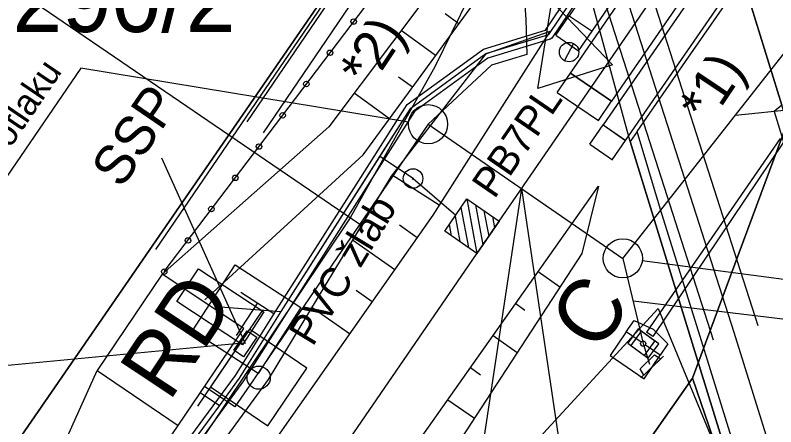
# Model space of a CAD drawing. Extents: x -558199 to -558019, y -1073463 to -1073248.
# Drawn here: x -558155.77 to -558136.35, y -1073413.56 to -1073403.06 of the extents above; entities that cross this region are included whole.
import ezdxf

# ---------------------------------------------------------------- set-up
doc = ezdxf.new("R2010")
doc.units = 0
for name, color, linetype in [('Default', 7, 'Continuous'), ('DWG-zabzař', 7, 'Continuous'), ('El2015-Svršek - součást', 7, 'Continuous'), ('El2015-Zabzař nadzemní', 7, 'Continuous'), ('Elektro nadzemní', 7, 'Continuous'), ('Kolej', 7, 'Continuous'), ('Komunikace', 7, 'Continuous'), ('Nová kabelizace', 7, 'Continuous'), ('nové prvky ZZ', 7, 'Continuous'), ('Plot - zábradlí', 7, 'Continuous'), ('PS01_PS02_nové prvky ZZ', 7, 'Continuous'), ('Přejezd - štěrkové lože', 7, 'Continuous'), ('Sdělovací objekt', 7, 'Continuous'), ('Sonda - šrafa - vrstevnice', 7, 'Continuous'), ('Stavba', 7, 'Continuous'), ('Svazek obcí údolí Desné', 7, 'Continuous'), ('Svazek obcí-chráničky', 7, 'Continuous'), ('Svazek obcí-elektro', 7, 'Continuous'), ('Svazek obcí-zabezpečovací', 7, 'Continuous'), ('Svazek obcí-zabezpečovací_nadzemní', 7, 'Continuous'), ('Svršek součást', 7, 'Continuous'), ('Terén', 7, 'Continuous'), ('Vrstva 15', 7, 'Continuous'), ('Vrstva 18', 7, 'Continuous'), ('zab zař nové popis a prvky', 7, 'Continuous'), ('ŠPVS - kanalizace', 7, 'Continuous')]:
    doc.layers.add(name, color=color, linetype=linetype)

msp = doc.modelspace()

# ---------------------------------------------------------------- linework, layer by layer
at = {"layer": 'Default'}
for p, q in [((-558141.959, -1073403.569), (-558141.62, -1073403.074)), ((-558141.62, -1073403.074), (-558141.038, -1073403.468)), ((-558141.377, -1073403.963), (-558141.038, -1073403.468)), ((-558141.959, -1073403.569), (-558141.38, -1073403.966)), ((-558154.086, -1073404.411), (-558157.347, -1073409.172)), ((-558141.926, -1073405.034), (-558141.587, -1073404.539)), ((-558141.587, -1073404.539), (-558140.536, -1073405.256)), ((-558141.926, -1073405.034), (-558140.875, -1073405.751)), ((-558140.875, -1073405.751), (-558140.536, -1073405.256)), ((-558141.094, -1073406.353), (-558140.755, -1073405.858)), ((-558140.755, -1073405.858), (-558140.178, -1073406.254)), ((-558141.094, -1073406.353), (-558140.517, -1073406.749)), ((-558140.519, -1073406.752), (-558140.18, -1073406.257))]:
    msp.add_line(p, q, dxfattribs=at)
for points in [[(-558130.328, -1073420.145), (-558131.489, -1073419.211), (-558132.265, -1073417.928), (-558133.167, -1073415.078), (-558134.705, -1073410.166), (-558136.19, -1073405.354), (-558137.19, -1073402.13), (-558138.301, -1073398.037), (-558138.619, -1073396.923), (-558140.033, -1073392.586), (-558141.446, -1073388.086), (-558141.737, -1073387.169), (-558144.083, -1073379.873)], [(-558134.819, -1073423.23), (-558136.982, -1073416.266), (-558138.481, -1073411.422), (-558140.066, -1073406.285), (-558141.174, -1073402.236), (-558142.21, -1073398.929), (-558143.82, -1073393.811), (-558145.559, -1073388.359), (-558147.912, -1073380.994)]]:
    msp.add_lwpolyline(points, dxfattribs=at)
at = {"layer": 'DWG-zabzař'}
for p, q in [((-558142.8, -1073399.77), (-558145.05, -1073404.38)), ((-558145.05, -1073404.38), (-558147.21, -1073408.23)), ((-558147.21, -1073408.23), (-558154.78, -1073419.51))]:
    msp.add_line(p, q, dxfattribs=at)
at = {"layer": 'El2015-Svršek - součást'}
for p, q in [((-558144.233, -1073407.749), (-558143.975, -1073409.139)), ((-558144.383, -1073407.967), (-558144.194, -1073408.989)), ((-558144.014, -1073407.899), (-558143.825, -1073408.921)), ((-558144.533, -1073408.186), (-558144.412, -1073408.839)), ((-558143.796, -1073408.049), (-558143.675, -1073408.702)), ((-558143.577, -1073408.199), (-558143.525, -1073408.483)), ((-558144.683, -1073408.404), (-558144.631, -1073408.688))]:
    msp.add_line(p, q, dxfattribs=at)
msp.add_lwpolyline([(-558143.409, -1073408.315), (-558143.975, -1073409.139), (-558144.799, -1073408.573), (-558144.233, -1073407.749)], close=True, dxfattribs=at)
at = {"layer": 'El2015-Zabzař nadzemní'}
msp.add_line((-558145.621, -1073407.249), (-558145.593, -1073407.207), dxfattribs=at)
msp.add_circle((-558145.607, -1073407.228), 0.25, dxfattribs=at)
at = {"layer": 'Elektro nadzemní'}
msp.add_lwpolyline([(-558151.637, -1073410.369), (-558151.088, -1073409.534), (-558149.417, -1073410.633), (-558149.966, -1073411.468), (-558151.637, -1073410.369)], dxfattribs=at)
at = {"layer": 'Kolej'}
msp.add_lwpolyline([(-558166.192, -1073441.436), (-558164.779, -1073439.38), (-558155.66, -1073426.127), (-558147.216, -1073413.854), (-558143.692, -1073408.727), (-558141.06, -1073404.904), (-558137.302, -1073399.438), (-558134.569, -1073395.461), (-558131.717, -1073391.307), (-558124.893, -1073381.375), (-558115.4, -1073367.564), (-558109.636, -1073359.184)], dxfattribs=at)
at = {"layer": 'Komunikace'}
for points in [[(-558134.582, -1073423.154), (-558136.753, -1073416.165), (-558138.246, -1073411.366), (-558139.293, -1073408.016), (-558139.888, -1073406.031), (-558138.651, -1073404.246), (-558137.19, -1073402.13), (-558136.19, -1073405.354), (-558136.385, -1073405.515), (-558134.943, -1073410.228), (-558133.406, -1073415.122), (-558132.477, -1073418.012), (-558131.667, -1073419.37), (-558130.464, -1073420.348)], [(-558139.888, -1073406.031), (-558140.066, -1073406.285), (-558138.481, -1073411.422), (-558136.982, -1073416.266), (-558134.819, -1073423.23)]]:
    msp.add_lwpolyline(points, dxfattribs=at)
at = {"layer": 'Nová kabelizace'}
msp.add_line((-558140.251, -1073409.265), (-558139.73, -1073411.44), dxfattribs=at)
for points in [[(-558143.327, -1073399.376), (-558144.071, -1073400.565), (-558142.86, -1073401.332), (-558142.728, -1073403.163), (-558142.702, -1073404.06), (-558143.604, -1073404.335), (-558145.224, -1073405.842), (-558149.771, -1073412.504), (-558150.161, -1073413.052), (-558150.928, -1073412.531)], [(-558145.224, -1073405.842), (-558140.251, -1073409.265), (-558135.564, -1073403.303), (-558135.378, -1073404.935)]]:
    msp.add_lwpolyline(points, dxfattribs=at)
at = {"layer": 'nové prvky ZZ'}
for p, q in [((-558136.235, -1073406.21), (-558139.648, -1073411.145)), ((-558136.135, -1073406.278), (-558139.483, -1073411.258)), ((-558149.889, -1073411.45), (-558152.018, -1073406.706)), ((-558139.483, -1073411.258), (-558139.648, -1073411.145)), ((-558139.73, -1073411.44), (-558139.568, -1073411.966)), ((-558139.79, -1073412.313), (-558139.212, -1073411.759))]:
    msp.add_line(p, q, dxfattribs=at)
for points in [[(-558139.786, -1073411.402), (-558140.163, -1073411.143), (-558139.965, -1073410.854), (-558139.476, -1073411.069), (-558139.099, -1073411.448), (-558139.297, -1073411.737), (-558139.675, -1073411.478)], [(-558149.598, -1073411.28), (-558149.935, -1073411.776), (-558150.184, -1073411.608), (-558149.847, -1073411.112), (-558149.598, -1073411.28)], [(-558139.786, -1073411.402), (-558140.163, -1073411.143), (-558140.573, -1073411.741), (-558139.708, -1073412.335), (-558139.297, -1073411.737), (-558139.675, -1073411.478)]]:
    msp.add_lwpolyline(points, dxfattribs=at)
for points in [[(-558139.335, -1073411.449), (-558139.861, -1073411.067), (-558140.125, -1073411.431), (-558139.6, -1073411.813)], [(-558139.436, -1073411.376), (-558139.78, -1073411.126), (-558140.044, -1073411.49), (-558139.701, -1073411.74)], [(-558139.718, -1073412.244), (-558139.81, -1073412.082), (-558139.441, -1073411.73), (-558139.284, -1073411.828)]]:
    msp.add_lwpolyline(points, close=True, dxfattribs=at)
msp.add_circle((-558139.73, -1073411.44), 0.0675, dxfattribs=at)
msp.add_circle((-558139.73, -1073411.44), 0.0675, dxfattribs=at)
msp.add_circle((-558139.73, -1073411.44), 0.0675, dxfattribs=at)
at = {"layer": 'Plot - zábradlí'}
msp.add_lwpolyline([(-558148.77, -1073381.259), (-558144.391, -1073397.612), (-558152.184, -1073409.04)], dxfattribs=at)
at = {"layer": 'Přejezd - štěrkové lože'}
for p, q in [((-558141.509, -1073403.786), (-558141.737, -1073404.218)), ((-558141.509, -1073403.786), (-558141.737, -1073404.218)), ((-558144.937, -1073407.912), (-558146.143, -1073407.146)), ((-558145.501, -1073408.738), (-558145.953, -1073408.42)), ((-558146.076, -1073409.556), (-558147.15, -1073408.801)), ((-558142.41, -1073409.603), (-558141.856, -1073409.994)), ((-558146.652, -1073410.373), (-558147.059, -1073410.087)), ((-558147.227, -1073411.192), (-558148.189, -1073410.515)), ((-558142.987, -1073410.42), (-558142.753, -1073410.585)), ((-558143.563, -1073411.237), (-558142.949, -1073411.67)), ((-558144.14, -1073412.054), (-558143.882, -1073412.236)), ((-558144.716, -1073412.871), (-558144.042, -1073413.347))]:
    msp.add_line(p, q, dxfattribs=at)
for points in [[(-558141.62, -1073403.074), (-558141.038, -1073403.468), (-558137.627, -1073398.494), (-558138.208, -1073398.104)], [(-558141.587, -1073404.539), (-558137.832, -1073399.076), (-558136.782, -1073399.796), (-558140.536, -1073405.256)], [(-558140.755, -1073405.858), (-558140.18, -1073406.257), (-558136.769, -1073401.319), (-558137.351, -1073400.919)]]:
    msp.add_lwpolyline(points, close=True, dxfattribs=at)
for points in [[(-558143.119, -1073399.397), (-558142.066, -1073402.711), (-558140.518, -1073404.324), (-558142.42, -1073404.935), (-558142.066, -1073402.711)], [(-558143.119, -1073399.397), (-558142.066, -1073402.711), (-558140.518, -1073404.324), (-558142.42, -1073404.935), (-558142.066, -1073402.711)], [(-558142.117, -1073403.477), (-558143.754, -1073404.051), (-558146.162, -1073407.17), (-558149.304, -1073412.355), (-558152.838, -1073417.196), (-558154.313, -1073420.055), (-558157.793, -1073424.718)], [(-558142.117, -1073403.477), (-558145.099, -1073408.167), (-558148.507, -1073413.01), (-558157.055, -1073425.159)], [(-558154.327, -1073427.065), (-558145.987, -1073414.672), (-558140.875, -1073407.427)], [(-558140.875, -1073407.427), (-558141.298, -1073409.138), (-558145.289, -1073415.259), (-558153.522, -1073427.772)]]:
    msp.add_lwpolyline(points, dxfattribs=at)
msp.add_circle((-558141.624, -1073404.001), 0.248, dxfattribs=at)
msp.add_circle((-558141.624, -1073404.001), 0.248, dxfattribs=at)
at = {"layer": 'Sdělovací objekt'}
for p, q in [((-558150.002, -1073410.124), (-558149.163, -1073410.669)), ((-558149.583, -1073410.397), (-558150.127, -1073411.235))]:
    msp.add_line(p, q, dxfattribs=at)
msp.add_lwpolyline([(-558150.15, -1073409.433), (-558148.472, -1073410.521), (-558149.56, -1073412.199), (-558151.238, -1073411.111), (-558150.15, -1073409.433)], dxfattribs=at)
at = {"layer": 'Sonda - šrafa - vrstevnice'}
for p, q in [((-558144.441, -1073403.282), (-558144.788, -1073403.029)), ((-558145.031, -1073404.09), (-558145.909, -1073403.449)), ((-558145.621, -1073404.897), (-558145.976, -1073404.638)), ((-558146.211, -1073405.705), (-558147.109, -1073405.049))]:
    msp.add_line(p, q, dxfattribs=at)
at = {"layer": 'Stavba'}
msp.add_lwpolyline([(-558152.011, -1073409.668), (-558153.676, -1073412.127), (-558151.605, -1073413.53), (-558149.929, -1073411.055), (-558152.011, -1073409.668)], dxfattribs=at)
at = {"layer": 'Svazek obcí údolí Desné'}
for points in [[(-558171.538, -1073437.753), (-558157.08, -1073415.91), (-558144.45, -1073397.61), (-558143.83, -1073396.83), (-558140.29, -1073392.34), (-558139.67, -1073391.56), (-558138.4, -1073389.94), (-558132.32, -1073380.12), (-558131.71, -1073378.11), (-558115.469, -1073355.166)], [(-558100.193, -1073365.689), (-558100.88, -1073366.68), (-558101.24, -1073366.41), (-558106.08, -1073373.34), (-558109.37, -1073371.06), (-558120.48, -1073382.36), (-558123.3, -1073385.22), (-558134.85, -1073401.19), (-558135.09, -1073403.23), (-558138.47, -1073412.32), (-558161.279, -1073444.82)]]:
    msp.add_lwpolyline(points, dxfattribs=at)
at = {"layer": 'Svazek obcí-chráničky'}
for points in [[(-558154.594, -1073416.016), (-558151.277, -1073413.806), (-558150.144, -1073412.251), (-558149.077, -1073410.551), (-558147.061, -1073407.39), (-558145.756, -1073405.343), (-558143.808, -1073403.927), (-558142.223, -1073403.443), (-558137.803, -1073396.894), (-558137.219, -1073393.903), (-558135.426, -1073390.192), (-558133.151, -1073387.003), (-558129.565, -1073381.036), (-558128.701, -1073379.414), (-558127.762, -1073378.717), (-558122.644, -1073382.737), (-558121.705, -1073382.145)], [(-558121.571, -1073382.357), (-558122.66, -1073383.043), (-558127.766, -1073379.031), (-558128.507, -1073379.582), (-558129.345, -1073381.154), (-558129.723, -1073381.783), (-558132.298, -1073386.069), (-558132.941, -1073387.141), (-558135.21, -1073390.32), (-558136.979, -1073393.979), (-558137.39, -1073396.388), (-558137.575, -1073397.002), (-558142.061, -1073403.648), (-558142.108, -1073403.67), (-558143.694, -1073404.153), (-558145.57, -1073405.517), (-558149.936, -1073412.391), (-558151.101, -1073413.99), (-558154.456, -1073416.224)]]:
    msp.add_lwpolyline(points, dxfattribs=at)
at = {"layer": 'Svazek obcí-elektro'}
for points in [[(-558150.527, -1073410.501), (-558148.971, -1073410.618), (-558146.453, -1073406.668), (-558145.663, -1073405.43), (-558143.751, -1073404.04), (-558142.144, -1073403.55), (-558137.689, -1073396.948), (-558137.513, -1073396.367), (-558137.099, -1073393.941), (-558135.318, -1073390.256), (-558133.046, -1073387.072), (-558129.455, -1073381.095), (-558128.604, -1073379.498), (-558127.764, -1073378.874), (-558122.652, -1073382.89), (-558121.638, -1073382.251), (-558115.441, -1073375.378), (-558105.495, -1073362.037)], [(-558150.527, -1073410.501), (-558148.971, -1073410.618), (-558146.453, -1073406.668), (-558145.663, -1073405.43), (-558143.751, -1073404.04), (-558142.144, -1073403.55), (-558137.689, -1073396.948), (-558137.513, -1073396.367), (-558137.099, -1073393.941), (-558135.318, -1073390.256), (-558133.046, -1073387.072), (-558129.455, -1073381.095), (-558128.604, -1073379.498), (-558127.764, -1073378.874), (-558122.652, -1073382.89), (-558121.638, -1073382.251), (-558115.441, -1073375.378), (-558105.495, -1073362.037)], [(-558151.637, -1073410.369), (-558151.088, -1073409.534), (-558149.417, -1073410.633), (-558149.966, -1073411.468), (-558151.637, -1073410.369)]]:
    msp.add_lwpolyline(points, dxfattribs=at)
at = {"layer": 'Svazek obcí-zabezpečovací'}
for p, q in [((-558145.607, -1073407.228), (-558146.453, -1073406.668)), ((-558150.553, -1073413.027), (-558151.04, -1073412.696))]:
    msp.add_line(p, q, dxfattribs=at)
msp.add_lwpolyline([(-558169.949, -1073438.848), (-558167.958, -1073436.021), (-558157.458, -1073420.639), (-558154.525, -1073416.12), (-558151.189, -1073413.898), (-558150.553, -1073413.027), (-558150.04, -1073412.321), (-558148.971, -1073410.618), (-558145.663, -1073405.43), (-558143.751, -1073404.04), (-558142.144, -1073403.55), (-558137.689, -1073396.948), (-558137.513, -1073396.367), (-558137.099, -1073393.941), (-558135.318, -1073390.256), (-558133.046, -1073387.072), (-558129.455, -1073381.095), (-558128.604, -1073379.498), (-558127.764, -1073378.874), (-558122.652, -1073382.89), (-558121.638, -1073382.251), (-558115.441, -1073375.378), (-558105.495, -1073362.037)], dxfattribs=at)
at = {"layer": 'Svazek obcí-zabezpečovací_nadzemní'}
msp.add_line((-558145.607, -1073407.228), (-558144.516, -1073408.16), dxfattribs=at)
at = {"layer": 'Svršek součást'}
for p, q in [((-558149.453, -1073410.587), (-558151.111, -1073413.033)), ((-558149.784, -1073411.076), (-558150.78, -1073412.544)), ((-558148.316, -1073412.071), (-558149.784, -1073411.076)), ((-558149.311, -1073413.54), (-558148.316, -1073412.071)), ((-558150.78, -1073412.544), (-558149.311, -1073413.54))]:
    msp.add_line(p, q, dxfattribs=at)
msp.add_circle((-558149.549, -1073412.31), 0.296, dxfattribs=at)
at = {"layer": 'Terén'}
for points in [[(-558150.92, -1073410.321), (-558146.881, -1073406.623), (-558143.086, -1073401.426), (-558143.817, -1073399.396), (-558143.23, -1073398.366), (-558143.82, -1073393.811)], [(-558144.391, -1073397.612), (-558145.08, -1073400.075), (-558144.506, -1073401.579), (-558147.754, -1073405.91), (-558152.011, -1073409.668)], [(-558152.696, -1073428.173), (-558144.227, -1073415.844), (-558139.347, -1073410.546), (-558136.982, -1073416.266)], [(-558160.273, -1073422.611), (-558156.919, -1073419.317), (-558153.676, -1073412.127)], [(-558158.606, -1073423.971), (-558154.771, -1073419.542), (-558153.233, -1073415.919), (-558151.605, -1073413.53)]]:
    msp.add_lwpolyline(points, dxfattribs=at)
at = {"layer": 'Vrstva 15'}
for points in [[(-558171.538, -1073437.753), (-558157.08, -1073415.91), (-558144.45, -1073397.61), (-558143.83, -1073396.83), (-558140.29, -1073392.34), (-558139.67, -1073391.56), (-558138.4, -1073389.94), (-558132.32, -1073380.12), (-558131.71, -1073378.11), (-558115.469, -1073355.166)], [(-558100.193, -1073365.689), (-558100.88, -1073366.68), (-558101.24, -1073366.41), (-558106.08, -1073373.34), (-558109.37, -1073371.06), (-558120.48, -1073382.36), (-558123.3, -1073385.22), (-558134.85, -1073401.19), (-558135.09, -1073403.23), (-558138.47, -1073412.32), (-558161.279, -1073444.82)], [(-558161.279, -1073444.82), (-558138.47, -1073412.32), (-558132.91, -1073428.56), (-558133.56, -1073429.34), (-558133.31, -1073429.98), (-558133.35, -1073433.74), (-558133.63, -1073435.37), (-558148.119, -1073453.886)]]:
    msp.add_lwpolyline(points, dxfattribs=at)
for points in [[(-558144.45, -1073397.61), (-558157.08, -1073415.91), (-558161.06, -1073413.25), (-558166.05, -1073409.92), (-558148.41, -1073384.06)], [(-558138.47, -1073412.32), (-558135.09, -1073403.23), (-558135.05, -1073407.29), (-558131.47, -1073417.12), (-558130.91, -1073418.65), (-558126.8, -1073426.64), (-558129.35, -1073429.91), (-558131.5, -1073432.67), (-558132.91, -1073428.56)]]:
    msp.add_lwpolyline(points, close=True, dxfattribs=at)
at = {"layer": 'zab zař nové popis a prvky'}
for p, q in [((-558149.839, -1073405.784), (-558144.221, -1073397.511)), ((-558162.592, -1073397.742), (-558146.963, -1073408.39)), ((-558149.425, -1073406.065), (-558143.808, -1073397.792)), ((-558151.96, -1073409.604), (-558144.084, -1073399.213)), ((-558137.377, -1073405.609), (-558127.057, -1073404.553)), ((-558142.837, -1073407.485), (-558144.17, -1073416.297)), ((-558142.837, -1073407.485), (-558140.794, -1073421.28)), ((-558139.991, -1073410.353), (-558130.352, -1073411.501)), ((-558149.961, -1073411.432), (-558158.01, -1073412.193))]:
    msp.add_line(p, q, dxfattribs=at)
for points in [[(-558145.721, -1073405.786), (-558154.086, -1073404.411)], [(-558139.755, -1073409.322), (-558132.976, -1073410.212)]]:
    msp.add_lwpolyline(points, dxfattribs=at)
for centre, radius in [((-558147.122, -1073403.222), 0.07), ((-558147.122, -1073403.222), 0.07), ((-558147.727, -1073404.02), 0.07), ((-558147.727, -1073404.02), 0.07), ((-558148.332, -1073404.817), 0.07), ((-558148.332, -1073404.817), 0.07), ((-558145.224, -1073405.842), 0.5), ((-558148.936, -1073405.615), 0.07), ((-558148.936, -1073405.615), 0.07), ((-558149.541, -1073406.413), 0.07), ((-558149.541, -1073406.413), 0.07), ((-558150.146, -1073407.211), 0.07), ((-558150.146, -1073407.211), 0.07), ((-558150.756, -1073408.005), 0.07), ((-558150.756, -1073408.005), 0.07), ((-558151.353, -1073408.808), 0.07), ((-558151.353, -1073408.808), 0.07), ((-558140.251, -1073409.265), 0.5), ((-558151.96, -1073409.604), 0.07), ((-558151.96, -1073409.604), 0.07)]:
    msp.add_circle(centre, radius, dxfattribs=at)
at = {"layer": 'ŠPVS - kanalizace'}
for p, q in [((-558136.793, -1073410.987), (-558141.218, -1073397.198)), ((-558137.935, -1073411.353), (-558142.36, -1073397.564))]:
    msp.add_line(p, q, dxfattribs=at)
msp.add_lwpolyline([(-558142.53, -1073396.09), (-558141.8, -1073397.5), (-558137.42, -1073411.15), (-558133.1, -1073424.98)], dxfattribs=at)

# ---------------------------------------------------------------- texts
at = {"layer": 'El2015-Zabzař nadzemní'}
for s, height, rotation, p in [('PB7PL', 0.75, 55.4976, (-558143.532, -1073407.773)), ('RD', 1.6, 56.3993, (-558151.833, -1073412.949))]:
    msp.add_text(s, height=height, rotation=rotation, dxfattribs=at).set_placement(p)
at = {"layer": 'nové prvky ZZ'}
msp.add_text('SSP', height=1, rotation=55.6377, dxfattribs=at).set_placement((-558153.054, -1073407.512))
at = {"layer": 'PS01_PS02_nové prvky ZZ'}
msp.add_text('C', height=1.6, rotation=55.7527, dxfattribs=at).set_placement((-558140.879, -1073411.711))
at = {"layer": 'Svazek obcí-chráničky'}
msp.add_text('PVC žlab', height=0.75, rotation=58.785, dxfattribs=at).set_placement((-558148.169, -1073411.539))
at = {"layer": 'Vrstva 18'}
msp.add_text('290/2', height=1.7, dxfattribs=at).set_placement((-558155.83, -1073403.49))
at = {"layer": 'zab zař nové popis a prvky'}
for s, height, rotation, p in [('*2)', 1, 56.3059, (-558146.711, -1073404.961)), ('jáma protlaku', 0.672, 55.8269, (-558157.581, -1073408.954)), ('*1)', 1, 56.3059, (-558138.04, -1073405.877))]:
    msp.add_text(s, height=height, rotation=rotation, dxfattribs=at).set_placement(p)

doc.saveas('drawing.dxf')
